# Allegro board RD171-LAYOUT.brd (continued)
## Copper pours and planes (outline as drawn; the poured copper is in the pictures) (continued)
SIGN360 on TOP: 260.67,32 260.65,32 260.64,32.01 257.66,34.99 257.65,35 257.65,35.02 257.65,41.79 257.58,42.16 257.36,42.49 249.69,50.16 249.38,50.37 248.99,50.45 237.97,50.45 237.95,50.45 237.94,50.46 235.31,53.09 235.3,53.1 235.3,53.12 235.3,65.63 235.3,65.65 235.31,65.66 236.99,67.34 237,67.35 237.02,67.35 240.23,67.35 240.25,67.35 240.26,67.34 245.45,62.15 245.62,62.04 245.81,62 247.43,62 247.62,61.96 247.78,61.85 249.96,59.62 250,59.43 250,58.61 250.04,58.42 250.15,58.25 263.56,44.84 263.63,44.74 263.65,44.63 263.65,32.82 263.65,32.8 263.64,32.79 262.86,32.01 262.85,32 262.83,32
SIGN360 on BOTTOM: 237.97,50.45 237.95,50.45 237.94,50.46 235.31,53.09 235.3,53.1 235.3,53.12 235.3,65.63 235.3,65.65 235.31,65.66 236.99,67.34 237,67.35 237.02,67.35 240.23,67.35 240.25,67.35 240.26,67.34 245.45,62.15 245.62,62.04 245.81,62 247.43,62 247.56,61.98 247.78,61.85 249.85,59.78 249.93,59.68 250,59.43 250,58.05 249.96,57.86 249.85,57.69 247.81,55.65 247.64,55.54 247.45,55.5 247.11,55.5 246.92,55.46 246.75,55.35 241.86,50.46 241.85,50.45 241.83,50.45
SIGN364 on TOP: 73.75,51.2 73.64,51.24 73.6,51.35 73.6,56.05 73.64,56.16 73.75,56.2 77.55,56.2 77.66,56.16 77.7,56.05 77.7,51.35 77.66,51.24 77.55,51.2
SIGN364 on BOTTOM: 74.6,51.2 73.6,52.2 73.6,55.2 74.6,56.2 77.55,56.2 77.66,56.16 77.7,56.05 77.7,51.35 77.66,51.24 77.55,51.2
SIGN364 on BOTTOM: 103.8,29.65 103.76,29.66 103.75,29.7 103.75,34.65 103.76,34.69 103.8,34.7 105.78,34.7 105.8,34.7 105.81,34.69 107.39,33.11 107.4,33.1 107.4,33.08 107.4,30.97 107.4,30.95 107.39,30.94 106.11,29.66 106.1,29.65 106.08,29.65
SIGN366 on TOP (solid shape): 130.71,70.31 131.05,70.37 131.12,70.03 129.81,68.11 129.6,68 129.4,68.1 128.02,69.97 127.98,70.04 127.97,70.12 128.14,70.36 128.42,70.27 128.69,69.91 130.45,69.94
SIGN366 on BOTTOM: 130.18,68 130.07,67.95 129.97,68 126.45,71.52 126.4,71.62 126.45,71.73 128.92,74.2 129.03,74.25 129.13,74.2 132.65,70.68 132.7,70.58 132.65,70.47
SIGN369 on BOTTOM: 181.25,59 181.14,59.04 181.1,59.15 181.1,63.75 181.14,63.86 181.25,63.9 184.75,63.9 184.86,63.86 184.9,63.75 184.9,59.15 184.86,59.04 184.75,59
SIGN371 on TOP (solid shape): 117.41,49.21 117.75,49.27 117.82,48.93 116.51,47.01 116.3,46.9 116.1,47 114.72,48.87 114.68,48.94 114.67,49.02 114.84,49.26 115.12,49.17 115.39,48.81 117.15,48.84
SIGN371 on BOTTOM: 113.76,48.1 113.65,48.14 113.61,48.25 113.61,51.75 113.65,51.86 113.76,51.9 120.74,51.9 120.85,51.86 120.89,51.75 120.89,48.25 120.85,48.14 120.74,48.1
SIGN373 on TOP (solid shape): 183.83,86.88 184.03,87.17 184.32,86.97 184.71,84.68 184.64,84.46 184.42,84.39 182.71,84.68 182.13,84.78 181.98,84.86 181.92,85.02 182.01,85.21 182.22,85.27 182.66,85.19 183.91,86.44
SIGN373 on BOTTOM: 178.9,84.75 178.79,84.79 178.75,84.9 178.75,88.4 178.79,88.51 178.9,88.55 182.35,88.55 182.46,88.51 182.5,88.4 182.5,84.9 182.46,84.79 182.35,84.75
N05004 on TOP, BOTTOM: 141.91,121.1 141.91,126.5 145.09,126.5 145.09,121.1
N07003 on TOP: 266.57,82.25 266.55,82.25 266.54,82.26 260.17,88.63 260.04,88.72 259.88,88.75 237.16,88.75 236.97,88.79 236.8,88.9 235.31,90.39 235.3,90.4 235.3,90.42 235.3,104.23 235.3,104.25 235.31,104.26 236.99,105.94 237,105.95 237.02,105.95 240.23,105.95 240.25,105.95 240.26,105.94 245.45,100.75 245.62,100.64 245.81,100.6 247.43,100.6 247.62,100.56 247.78,100.45 249.85,98.38 249.96,98.22 250,98.03 250,96.51 250.04,96.32 250.15,96.15 251.45,94.85 251.62,94.74 251.81,94.7 263.88,94.7 263.9,94.7 263.91,94.69 269.33,89.27 269.38,89.16 269.38,83.12 269.37,83.1 269.36,83.09 268.43,82.26 268.41,82.25 268.39,82.25
N07083 on BOTTOM: 256.98,60.85 256.87,60.89 256.82,61 256.82,62.8 256.87,62.91 256.98,62.95 262.67,62.95 262.77,62.98 262.81,63.01 264.24,64.44 264.29,64.53 264.3,64.58 264.3,78.72 264.27,78.82 264.24,78.86 263.66,79.44 263.59,79.48 263.52,79.5 258.37,79.5 258.34,79.51 258.32,79.55 258.32,81.55 258.34,81.59 258.38,81.6 273.18,81.6 273.2,81.6 273.21,81.59 273.74,81.06 273.75,81.05 273.75,81.03 273.75,73.85 273.76,73.8 273.79,73.76 274.19,73.36 274.26,73.32 274.33,73.3 279.03,73.3 279.05,73.3 279.06,73.29 279.53,72.82 279.54,72.8 279.53,72.77 279.55,72.75 279.55,72.73 279.55,65.02 279.55,65 279.54,64.99 279.01,64.46 279,64.45 278.98,64.45 274.73,64.45 274.63,64.42 274.59,64.39 271.09,60.89 271.05,60.86 270.99,60.85
N07119 on BOTTOM: 256.98,98.85 256.87,98.89 256.82,99 256.82,100.8 256.87,100.91 256.98,100.95 262.67,100.95 262.74,100.97 262.81,101.01 264.24,102.44 264.28,102.51 264.3,102.58 264.3,116.72 264.28,116.79 264.24,116.86 263.66,117.44 263.59,117.48 263.52,117.5 258.37,117.5 258.34,117.51 258.32,117.55 258.32,119.55 258.34,119.59 258.38,119.6 264.99,119.6 265.18,119.64 265.35,119.75 268.64,123.04 268.65,123.05 268.67,123.05 273.43,123.05 273.45,123.05 273.46,123.04 273.73,122.77 273.75,122.75 273.75,122.73 273.75,101.61 273.74,101.56 273.71,101.51 271.09,98.89 271.05,98.86 270.99,98.85
N07369 on TOP: 245.85,102.27 245.74,102.29 245.64,102.36 243.4,104.6 243.29,104.77 243.25,104.96 243.25,117.29 243.29,117.48 243.4,117.65 245.19,119.44 245.2,119.45 245.22,119.45 249.08,119.45 249.1,119.45 249.11,119.44 250.05,118.5 250.2,118.15 250.55,118 250.6,117.95 250.71,117.78 250.75,117.59 250.75,110.58 250.77,110.51 250.81,110.44 253.53,107.72 253.75,107.39 253.82,107.01 253.82,102.42 253.78,102.31 253.68,102.27
N07369 on BOTTOM: 252.32,98.85 252.3,98.85 252.29,98.86 249.03,102.12 248.86,102.23 248.67,102.27 245.85,102.27 245.74,102.29 245.64,102.36 243.4,104.6 243.29,104.77 243.25,104.96 243.25,117.29 243.27,117.42 243.4,117.65 245.19,119.44 245.2,119.45 245.22,119.45 249.08,119.45 249.11,119.44 249.8,118.75 249.88,118.64 249.95,118.39 249.95,108.53 249.99,108.34 250.1,108.17 251.2,107.07 251.36,106.96 251.55,106.92 253.78,106.92 253.81,106.91 253.82,106.88 253.82,102.42 253.82,102.41 253.82,98.9 253.81,98.86 253.77,98.85
N07429 on TOP: 237.02,70.3 236.99,70.31 235.31,71.99 235.3,72.02 235.3,76.01 235.3,76.03 235.31,76.08 235.3,76.15 235.3,86.53 235.3,86.55 235.31,86.56 236.85,88.1 236.96,88.18 237.21,88.25 254.78,88.25 254.82,88.23 255.31,87.74 255.32,87.72 255.32,87.7 255.32,82.6 255.32,82.58 255.31,82.56 255.06,82.31 255.05,82.3 255.03,82.3 251.96,82.3 251.77,82.26 251.6,82.15 251.31,81.86 251.27,81.79 251.25,81.72 251.25,80.55 251.24,80.51 251.2,80.5 250.18,80.5 250.16,80.5 250.14,80.51 249.5,81.15 247.15,82.21 244.8,81.15 244.79,81.15 242.83,79.08 242.75,78.69 242.75,77.55 242.75,77.5 242.75,72.02 242.75,72 242.74,71.99 241.06,70.31 241.03,70.3
N07429 on BOTTOM: 237.02,70.3 236.99,70.31 235.31,71.99 235.3,72.02 235.3,76.01 235.3,76.03 235.31,76.08 235.3,76.13 235.3,76.15 235.3,86.53 235.3,86.55 235.31,86.56 236.85,88.1 237.02,88.21 237.21,88.25 254.78,88.25 254.8,88.25 254.81,88.24 255.31,87.74 255.32,87.72 255.32,87.7 255.32,79.56 255.31,79.52 255.28,79.51 251.16,79.51 251.14,79.51 251.13,79.52 250.99,79.66 250.96,79.7 249.5,81.15 249.5,81.15 247.15,82.21 244.8,81.15 244.79,81.15 242.83,79.08 242.75,78.69 242.75,72.02 242.75,72 242.74,71.99 241.06,70.31 241.03,70.3
N14553110 on BOTTOM: 212.02,1 212,1 211.99,1.01 211.51,1.49 211.5,1.5 211.5,1.52 211.5,2.83 211.51,2.86 211.51,4.84 211.51,4.86 211.52,4.87 211.74,5.09 211.75,5.1 211.77,5.1 215.83,5.1 215.85,5.1 215.86,5.09 216.08,4.87 216.09,4.86 216.09,4.84 216.09,4.3 216.47,3.38 217.4,3 218.31,3.38 218.69,4.3 218.69,4.82 218.69,4.84 218.7,4.85 218.94,5.09 218.95,5.1 218.97,5.1 237.84,5.1 238.09,5.17 238.2,5.25 243.74,10.79 243.79,10.88 243.8,10.93 243.8,12.9 243.81,12.94 243.85,12.95 245.15,12.95 245.19,12.94 245.2,12.9 245.2,10.37 245.2,10.35 245.19,10.34 243.66,8.81 243.61,8.72 243.6,8.67 243.6,4.1 243.59,4.06 243.55,4.05 242.88,4.05 242.78,4.02 242.74,3.99 239.76,1.01 239.75,1 239.73,1
N14557584 on BOTTOM: 180.17,14.25 180.15,14.25 180.14,14.26 179.46,14.94 179.45,14.95 179.45,14.97 179.45,15.36 179.46,15.4 179.5,15.41 181.4,15.41 181.44,15.4 181.45,15.36 181.45,14.82 181.45,14.8 181.44,14.79 180.91,14.26 180.9,14.25 180.88,14.25
N14557584 on BOTTOM: 190.82,14.55 190.8,14.55 190.79,14.56 190.41,14.94 190.4,14.95 190.4,14.97 190.4,17.6 190.41,17.64 190.45,17.65 193.56,17.65 193.6,17.64 193.62,17.6 193.62,15.78 193.61,15.76 193.6,15.74 192.42,14.56 192.41,14.55 192.39,14.55
N14565980 on TOP: 200.75,29.9 200.71,29.91 200.7,29.95 200.7,30.79 200.7,30.81 200.71,30.82 201.15,31.26 201.15,31.5 201.15,31.52 201.16,31.54 201.31,31.69 201.33,31.7 201.35,31.7 202.45,31.7 202.47,31.7 202.49,31.69 202.64,31.54 202.65,31.52 202.65,31.5 202.65,30.4 202.65,30.38 202.64,30.36 202.49,30.21 202.47,30.2 202.45,30.2 202.21,30.2 201.92,29.91 201.91,29.9 201.89,29.9
N16785059 on BOTTOM: 212.1,28.1 212.08,28.1 212.06,28.11 210.58,29.59 210.52,29.63 210.44,29.65 208.8,29.65 208.78,29.65 208.76,29.67 208.48,29.94 208.42,29.98 208.34,30 207.17,30 207.15,30 206.81,30.34 206.8,30.35 206.8,30.37 206.8,31.63 206.8,31.65 206.82,31.67 207.14,31.99 207.15,32 207.17,32 212.75,32 212.79,31.99 212.8,31.95 212.8,30.18 212.83,30.08 212.86,30.04 213.04,29.86 213.08,29.79 213.1,29.72 213.1,28.15 213.09,28.11 213.05,28.1

Small or netless copper shapes (teardrops, artwork), in the pictures only: 155 on TOP, 150 on BOTTOM, 34 on CONDUCTIVE3, 28 on CONDUCTIVE4

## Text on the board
Ref Des/Silkscreen Top: TP7 | RV1 | TP2 | Q1 | T3 | HS3 | TP43 | TP1 | R73 | TP4 | R74 | D39 | HS1 | TP39 | D38 | TP6 | D33 | R173 | TP38 | TP5 | 8 | 1 | T2 | IC2 | R174 | R198 | Q2 | R133 | R132 | 4 | 5 | R28 | R175 | Q3 | R83 | R176 | D36 | D37 | D43 | D42 | Q5 | TP11 | TP10 | R72 | R71 | TP8 | C103 | TP9 | TP3 | TP12 | D41 | IC4 | 14 | TP45 | Q6 | 7 | TP15 | D44 | D45 | TP80 | R33 | Q4 | R135 | R134 | HS4 | HS2 | HS6 | HS5 | D84 | 6 | 3 | T8 | T4 | T5 | T6 | R193 | 2 | R191 | R155 | R163 | R156 | R166 | IC15 | IC16 | 11 | TP29 | TP30 | 12 | 10 | 9 | TP18 | R152 | R196 | 13 | C104 | C106 | R151 | R197 | TP17 | C107 | C105 | TP22 | TP21 | R209 | R208 | CN8 | R70 | R63 | R65 | R180 | R53 | R51 | R140 | R118 | R119 | R141 | R182 | CN9 | R50 | R181 | R52 | R184 | TP25 | R207 | R58 | TP20 | R55 | R77 | R78 | TP42 | TP81 | R129 | TP31 | TP41 | CN6 | CN7 | CN1 | L11 | R138 | PRINTED SIDE | L12 | D50 | D48 | R86 | D32 | R87 | R82 | R172 | R177 | IC5 | R31 | C18 | TP44 | D40 | TP82 | C101 | C811 | D83 | R190 | R192 | Q9 | Q7 | IC6 | IC7 | TP19 | TP24 | C8 | TP28 | C9 | S | D | G | SW | Q80-D | T6-5 | T5-3 | T6-3 | T6-6 | VCC12R0 2 | 48VOUT | CSA | PN | CSB | Q1-G | OUTB1 | GDB | OUTA1 | GDA | VINAC | OUTD1 | Q3-G | VSENSE | OUTC1 | Q4-G | Q2-G | Q7-G | Q11-G | OUTE | Q9-G | LGND | PFC OUT | VCC12R0 1 | OR-G | OUTF | Q13-G | FOR CONTINUED PROTECTION AGAINST RISK OF FIRE. | HOT. TEST BEFORE | TOUCHING ON HEATSINKS | REPLACE ONLY WITH SAME TYPE | 250V T15AH | DC450V 2A | CAUTION
